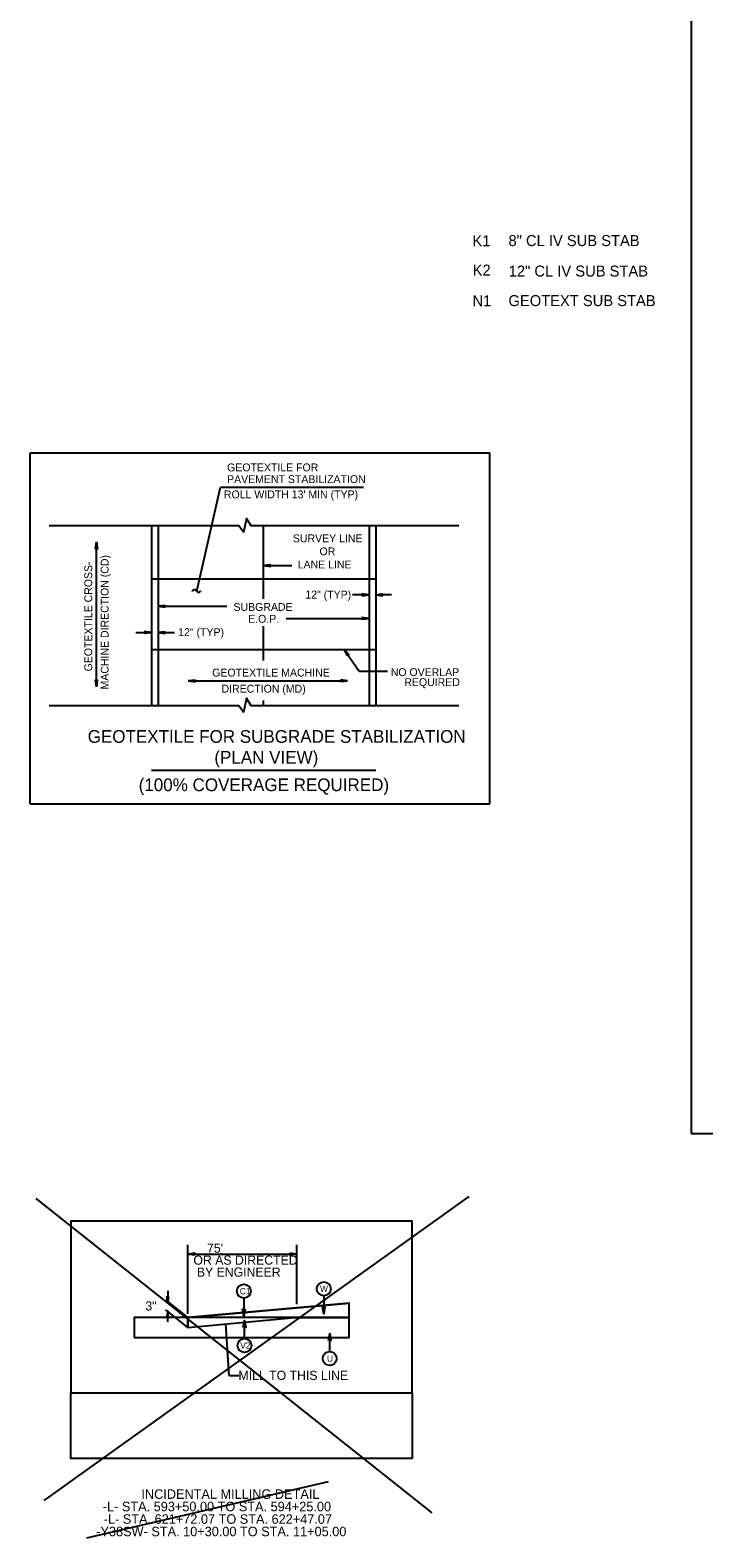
# Model space of a CAD drawing. Extents: x 2294342 to 2294901, y 719427 to 719941.
# Drawn here: x 2294341.9 to 2294456.7, y 719427.3 to 719684.2 of the extents above; entities that cross this region are included whole.
import ezdxf

# ---------------------------------------------------------------- set-up
doc = ezdxf.new("R2010")
doc.units = 0
for name, color, linetype in [('Exist Utilities Sanitary Sewer UG Line', 7, 'Continuous'), ('Old_Level_1', 7, 'Continuous'), ('Old_Level_11', 7, 'Continuous'), ('Old_Level_21', 7, 'Continuous'), ('Prop Dimension Text', 7, 'Continuous'), ('Prop Shade Light', 7, 'Continuous'), ('Raster_Level_2', 7, 'Continuous'), ('Sheet Cutting Line CELL', 7, 'Continuous'), ('Typical Detail Wedge2 CELL', 7, 'Continuous'), ('Typical ID Circle CELL', 7, 'Continuous'), ('Typical Pavement Slope CELL', 7, 'Continuous'), ('Typical Terminator CELL', 7, 'Continuous'), ('Typical Text General CELL', 7, 'Continuous'), ('Typical Text ID Circle CELL', 7, 'Continuous')]:
    doc.layers.add(name, color=color, linetype=linetype)

msp = doc.modelspace()

# ---------------------------------------------------------------- linework, layer by layer
at = {"layer": 'Exist Utilities Sanitary Sewer UG Line'}
msp.add_lwpolyline([(2294359.61, 719461.38), (2294396.24, 719461.38), (2294396.24, 719464.8), (2294359.61, 719464.8)], close=True, dxfattribs=at)
at = {"layer": 'Old_Level_1'}
for p, q in [((2294410.43, 719431.5), (2294342.9, 719485.08)), ((2294344.3, 719433.6), (2294416.73, 719485.43)), ((2294351.54, 719427.26), (2294392.73, 719436.87))]:
    msp.add_line(p, q, dxfattribs=at)
at = {"layer": 'Old_Level_11'}
for q in [(2294375.24, 719463.69), (2294377.46, 719454.94)]:
    msp.add_line((2294375.79, 719454.94), q, dxfattribs=at)
at = {"layer": 'Prop Dimension Text'}
for p, q in [((2294370.28, 719588.6), (2294374.35, 719606.29)), ((2294374.35, 719606.29), (2294398.7, 719606.29)), ((2294362.55, 719599.73), (2294362.55, 719569.07)), ((2294363.7, 719599.73), (2294363.7, 719569.07)), ((2294381.68, 719587.28), (2294381.68, 719599.73)), ((2294399.65, 719599.73), (2294399.65, 719569.07)), ((2294400.8, 719599.73), (2294400.8, 719569.07)), ((2294353.2, 719596.98), (2294353.03, 719595.77)), ((2294353.06, 719595.79), (2294353.2, 719596.98)), ((2294353.2, 719596.98), (2294353.08, 719595.82)), ((2294353.1, 719595.84), (2294353.2, 719596.98)), ((2294353.2, 719596.98), (2294353.13, 719595.86)), ((2294353.15, 719595.88), (2294353.2, 719596.98)), ((2294353.2, 719596.98), (2294353.17, 719595.91)), ((2294353.2, 719596.98), (2294353.36, 719595.77)), ((2294353.2, 719595.93), (2294353.2, 719596.98)), ((2294353.22, 719595.91), (2294353.2, 719596.98)), ((2294353.2, 719596.98), (2294353.24, 719595.88)), ((2294353.27, 719595.86), (2294353.2, 719596.98)), ((2294353.2, 719596.98), (2294353.29, 719595.84)), ((2294353.32, 719595.82), (2294353.2, 719596.98)), ((2294353.2, 719596.98), (2294353.34, 719595.79)), ((2294353.2, 719572.27), (2294353.2, 719596.98)), ((2294353.03, 719595.77), (2294353.2, 719595.93)), ((2294353.2, 719595.93), (2294353.36, 719595.77)), ((2294381.68, 719592.94), (2294382.89, 719593.11)), ((2294381.68, 719592.94), (2294382.86, 719593.08)), ((2294382.84, 719593.06), (2294381.68, 719592.94)), ((2294381.68, 719592.94), (2294382.82, 719593.04)), ((2294382.8, 719593.01), (2294381.68, 719592.94)), ((2294381.68, 719592.94), (2294382.78, 719592.99)), ((2294382.75, 719592.97), (2294381.68, 719592.94)), ((2294381.68, 719592.94), (2294382.89, 719592.78)), ((2294382.86, 719592.8), (2294381.68, 719592.94)), ((2294381.68, 719592.94), (2294382.84, 719592.83)), ((2294382.82, 719592.85), (2294381.68, 719592.94)), ((2294381.68, 719592.94), (2294382.8, 719592.87)), ((2294382.78, 719592.9), (2294381.68, 719592.94)), ((2294381.68, 719592.94), (2294382.75, 719592.92)), ((2294382.73, 719592.94), (2294381.68, 719592.94)), ((2294381.68, 719592.94), (2294386.49, 719592.94)), ((2294382.73, 719592.94), (2294382.89, 719593.11)), ((2294382.89, 719592.78), (2294382.73, 719592.94)), ((2294362.55, 719590.71), (2294400.8, 719590.71)), ((2294370.06, 719588.75), (2294370.49, 719588.45)), ((2294370.9, 719588.55), (2294370.98, 719588.7)), ((2294363.7, 719586.01), (2294364.91, 719586.18)), ((2294363.7, 719586.01), (2294364.89, 719586.15)), ((2294364.86, 719586.13), (2294363.7, 719586.01)), ((2294363.7, 719586.01), (2294364.84, 719586.11)), ((2294364.82, 719586.08), (2294363.7, 719586.01)), ((2294364.75, 719586.01), (2294364.91, 719586.18)), ((2294369.54, 719588.53), (2294369.59, 719588.64)), ((2294399.65, 719587.96), (2294396.84, 719587.96)), ((2294399.65, 719587.96), (2294398.44, 719588.13)), ((2294398.6, 719587.96), (2294398.44, 719588.13)), ((2294399.65, 719587.96), (2294398.44, 719587.8)), ((2294398.44, 719587.8), (2294398.6, 719587.96)), ((2294399.65, 719587.96), (2294398.46, 719588.1)), ((2294398.46, 719587.82), (2294399.65, 719587.96)), ((2294398.49, 719588.08), (2294399.65, 719587.96)), ((2294399.65, 719587.96), (2294398.49, 719587.85)), ((2294399.65, 719587.96), (2294398.51, 719588.06)), ((2294398.51, 719587.87), (2294399.65, 719587.96)), ((2294398.53, 719588.03), (2294399.65, 719587.96)), ((2294399.65, 719587.96), (2294398.53, 719587.89)), ((2294399.65, 719587.96), (2294398.55, 719588.01)), ((2294398.55, 719587.92), (2294399.65, 719587.96)), ((2294398.58, 719587.99), (2294399.65, 719587.96)), ((2294399.65, 719587.96), (2294398.58, 719587.94)), ((2294398.6, 719587.96), (2294399.65, 719587.96)), ((2294400.8, 719587.96), (2294402.01, 719588.13)), ((2294401.99, 719588.1), (2294400.8, 719587.96)), ((2294400.8, 719587.96), (2294401.96, 719588.08)), ((2294401.94, 719588.06), (2294400.8, 719587.96)), ((2294400.8, 719587.96), (2294401.92, 719588.03)), ((2294401.9, 719588.01), (2294400.8, 719587.96)), ((2294400.8, 719587.96), (2294401.87, 719587.99)), ((2294403.46, 719587.96), (2294400.8, 719587.96)), ((2294400.8, 719587.96), (2294402.01, 719587.8)), ((2294401.85, 719587.96), (2294400.8, 719587.96)), ((2294401.87, 719587.94), (2294400.8, 719587.96)), ((2294400.8, 719587.96), (2294401.9, 719587.92)), ((2294401.92, 719587.89), (2294400.8, 719587.96)), ((2294400.8, 719587.96), (2294401.94, 719587.87)), ((2294401.96, 719587.85), (2294400.8, 719587.96)), ((2294400.8, 719587.96), (2294401.99, 719587.82)), ((2294402.01, 719588.13), (2294401.85, 719587.96)), ((2294401.85, 719587.96), (2294402.01, 719587.8)), ((2294363.7, 719586.01), (2294364.8, 719586.06)), ((2294364.77, 719586.04), (2294363.7, 719586.01)), ((2294363.7, 719586.01), (2294364.91, 719585.85)), ((2294364.89, 719585.87), (2294363.7, 719586.01)), ((2294363.7, 719586.01), (2294364.86, 719585.9)), ((2294364.84, 719585.92), (2294363.7, 719586.01)), ((2294363.7, 719586.01), (2294364.82, 719585.95)), ((2294364.8, 719585.97), (2294363.7, 719586.01)), ((2294363.7, 719586.01), (2294364.77, 719585.99)), ((2294364.75, 719586.01), (2294363.7, 719586.01)), ((2294363.7, 719586.01), (2294375.44, 719586.01)), ((2294364.91, 719585.85), (2294364.75, 719586.01)), ((2294385.5, 719583.96), (2294399.65, 719583.96)), ((2294399.65, 719583.96), (2294398.44, 719584.12)), ((2294398.44, 719584.12), (2294398.6, 719583.96)), ((2294399.65, 719583.96), (2294398.44, 719583.79)), ((2294398.6, 719583.96), (2294398.44, 719583.79)), ((2294398.46, 719584.1), (2294399.65, 719583.96)), ((2294399.65, 719583.96), (2294398.46, 719583.82)), ((2294399.65, 719583.96), (2294398.49, 719584.07)), ((2294398.49, 719583.84), (2294399.65, 719583.96)), ((2294398.51, 719584.05), (2294399.65, 719583.96)), ((2294399.65, 719583.96), (2294398.51, 719583.86)), ((2294399.65, 719583.96), (2294398.53, 719584.03)), ((2294398.53, 719583.89), (2294399.65, 719583.96)), ((2294398.55, 719584), (2294399.65, 719583.96)), ((2294399.65, 719583.96), (2294398.55, 719583.91)), ((2294399.65, 719583.96), (2294398.58, 719583.98)), ((2294398.58, 719583.93), (2294399.65, 719583.96)), ((2294398.6, 719583.96), (2294399.65, 719583.96)), ((2294359.89, 719581.56), (2294362.55, 719581.56)), ((2294362.55, 719581.56), (2294361.34, 719581.72)), ((2294361.34, 719581.72), (2294361.5, 719581.56)), ((2294362.55, 719581.56), (2294361.34, 719581.39)), ((2294361.5, 719581.56), (2294361.34, 719581.39)), ((2294361.36, 719581.7), (2294362.55, 719581.56)), ((2294362.55, 719581.56), (2294361.36, 719581.42)), ((2294362.55, 719581.56), (2294361.39, 719581.67)), ((2294361.39, 719581.44), (2294362.55, 719581.56)), ((2294361.41, 719581.65), (2294362.55, 719581.56)), ((2294362.55, 719581.56), (2294361.41, 719581.46)), ((2294362.55, 719581.56), (2294361.43, 719581.63)), ((2294361.43, 719581.49), (2294362.55, 719581.56)), ((2294361.45, 719581.6), (2294362.55, 719581.56)), ((2294362.55, 719581.56), (2294361.45, 719581.51)), ((2294362.55, 719581.56), (2294361.48, 719581.58)), ((2294361.48, 719581.53), (2294362.55, 719581.56)), ((2294361.5, 719581.56), (2294362.55, 719581.56)), ((2294363.7, 719581.56), (2294364.91, 719581.72)), ((2294363.7, 719581.56), (2294364.89, 719581.7)), ((2294364.86, 719581.67), (2294363.7, 719581.56)), ((2294363.7, 719581.56), (2294364.84, 719581.65)), ((2294364.82, 719581.63), (2294363.7, 719581.56)), ((2294363.7, 719581.56), (2294364.8, 719581.6)), ((2294364.77, 719581.58), (2294363.7, 719581.56)), ((2294363.7, 719581.56), (2294366.51, 719581.56)), ((2294363.7, 719581.56), (2294364.91, 719581.39)), ((2294364.89, 719581.42), (2294363.7, 719581.56)), ((2294363.7, 719581.56), (2294364.86, 719581.44)), ((2294364.84, 719581.46), (2294363.7, 719581.56)), ((2294363.7, 719581.56), (2294364.82, 719581.49)), ((2294364.8, 719581.51), (2294363.7, 719581.56)), ((2294363.7, 719581.56), (2294364.77, 719581.53)), ((2294364.75, 719581.56), (2294363.7, 719581.56)), ((2294364.75, 719581.56), (2294364.91, 719581.72)), ((2294364.91, 719581.39), (2294364.75, 719581.56)), ((2294381.68, 719576.77), (2294381.68, 719582.65)), ((2294362.55, 719578.66), (2294400.8, 719578.66)), ((2294395.41, 719578.66), (2294395.98, 719577.58)), ((2294395.41, 719578.66), (2294396.25, 719577.77)), ((2294396.21, 719577.77), (2294395.41, 719578.66)), ((2294395.41, 719578.66), (2294396.18, 719577.78)), ((2294396.15, 719577.78), (2294395.41, 719578.66)), ((2294395.41, 719578.66), (2294396.12, 719577.79)), ((2294396.09, 719577.79), (2294395.41, 719578.66)), ((2294395.41, 719578.66), (2294396.05, 719577.8)), ((2294396.02, 719577.8), (2294395.41, 719578.66)), ((2294396.02, 719577.77), (2294395.41, 719578.66)), ((2294395.41, 719578.66), (2294396.01, 719577.74)), ((2294396, 719577.71), (2294395.41, 719578.66)), ((2294395.41, 719578.66), (2294396, 719577.67)), ((2294395.99, 719577.64), (2294395.41, 719578.66)), ((2294395.41, 719578.66), (2294395.99, 719577.61)), ((2294395.41, 719578.66), (2294397.99, 719574.96)), ((2294396.02, 719577.8), (2294395.98, 719577.58)), ((2294396.25, 719577.77), (2294396.02, 719577.8)), ((2294353.2, 719572.27), (2294353.03, 719573.48)), ((2294353.2, 719573.33), (2294353.03, 719573.48)), ((2294353.2, 719572.27), (2294353.06, 719573.46)), ((2294353.08, 719573.44), (2294353.2, 719572.27)), ((2294353.2, 719572.27), (2294353.1, 719573.42)), ((2294353.13, 719573.39), (2294353.2, 719572.27)), ((2294353.2, 719572.27), (2294353.15, 719573.37)), ((2294353.17, 719573.35), (2294353.2, 719572.27)), ((2294353.2, 719572.27), (2294353.36, 719573.48)), ((2294353.36, 719573.48), (2294353.2, 719573.33)), ((2294353.34, 719573.46), (2294353.2, 719572.27)), ((2294353.2, 719572.27), (2294353.31, 719573.44)), ((2294353.29, 719573.42), (2294353.2, 719572.27)), ((2294353.2, 719572.27), (2294353.27, 719573.39)), ((2294353.24, 719573.37), (2294353.2, 719572.27)), ((2294353.2, 719572.27), (2294353.22, 719573.35)), ((2294353.2, 719573.33), (2294353.2, 719572.27)), ((2294368.85, 719573.31), (2294370.06, 719573.47)), ((2294368.85, 719573.31), (2294370.04, 719573.45)), ((2294370.02, 719573.43), (2294368.85, 719573.31)), ((2294368.85, 719573.31), (2294369.99, 719573.4)), ((2294369.97, 719573.38), (2294368.85, 719573.31)), ((2294368.85, 719573.31), (2294369.95, 719573.35)), ((2294369.93, 719573.33), (2294368.85, 719573.31)), ((2294368.85, 719573.31), (2294370.06, 719573.14)), ((2294370.04, 719573.17), (2294368.85, 719573.31)), ((2294368.85, 719573.31), (2294370.02, 719573.19)), ((2294369.99, 719573.21), (2294368.85, 719573.31)), ((2294368.85, 719573.31), (2294369.97, 719573.24)), ((2294369.95, 719573.26), (2294368.85, 719573.31)), ((2294368.85, 719573.31), (2294369.93, 719573.28)), ((2294369.9, 719573.31), (2294368.85, 719573.31)), ((2294368.85, 719573.31), (2294396, 719573.31)), ((2294369.9, 719573.31), (2294370.06, 719573.47)), ((2294370.06, 719573.14), (2294369.9, 719573.31)), ((2294396, 719573.31), (2294394.78, 719573.47)), ((2294394.78, 719573.47), (2294394.94, 719573.31)), ((2294396, 719573.31), (2294394.78, 719573.15)), ((2294394.94, 719573.31), (2294394.78, 719573.15)), ((2294394.81, 719573.45), (2294396, 719573.31)), ((2294396, 719573.31), (2294394.81, 719573.17)), ((2294396, 719573.31), (2294394.83, 719573.43)), ((2294394.83, 719573.19), (2294396, 719573.31)), ((2294394.85, 719573.4), (2294396, 719573.31)), ((2294396, 719573.31), (2294394.85, 719573.21)), ((2294396, 719573.31), (2294394.88, 719573.38)), ((2294394.88, 719573.24), (2294396, 719573.31)), ((2294394.9, 719573.36), (2294396, 719573.31)), ((2294396, 719573.31), (2294394.9, 719573.26)), ((2294396, 719573.31), (2294394.92, 719573.33)), ((2294394.92, 719573.29), (2294396, 719573.31)), ((2294394.94, 719573.31), (2294396, 719573.31)), ((2294397.99, 719574.96), (2294402.78, 719574.96)), ((2294381.68, 719569.07), (2294381.68, 719569.94)), ((2294362.55, 719558.07), (2294400.8, 719558.07))]:
    msp.add_line(p, q, dxfattribs=at)
for points in [[(2294414.96, 719599.73), (2294379.56, 719599.73), (2294378.77, 719600.98), (2294378.26, 719598.64), (2294377.44, 719599.73), (2294345.12, 719599.73)], [(2294414.96, 719569.07), (2294379.56, 719569.07), (2294378.77, 719570.33), (2294378.26, 719567.99), (2294377.44, 719569.07), (2294345.12, 719569.07)]]:
    msp.add_lwpolyline(points, dxfattribs=at)
for centre, radius, start, end in [((2294369.87, 719588.53), 0.293, 48.0321, 157.831), ((2294370.65, 719588.65), 0.26, 230.477, 338.7625)]:
    msp.add_arc(centre, radius, start, end, dxfattribs=at)
at = {"layer": 'Prop Shade Light'}
msp.add_lwpolyline([(2294368.77, 719464.8), (2294368.77, 719463.09), (2294387.08, 719464.8), (2294396.24, 719464.8), (2294396.24, 719467.28)], close=True, dxfattribs=at)
at = {"layer": 'Raster_Level_2'}
for p, q in [((2294368.77, 719465.43), (2294368.77, 719477.22)), ((2294368.77, 719475.62), (2294387.35, 719475.62)), ((2294387.35, 719467.11), (2294387.35, 719477.22)), ((2294365.34, 719469.38), (2294365.34, 719467.59)), ((2294368.77, 719464.8), (2294365.04, 719467.83)), ((2294368.77, 719463.09), (2294365.04, 719466.12)), ((2294365.34, 719464.09), (2294365.34, 719465.88))]:
    msp.add_line(p, q, dxfattribs=at)
at = {"layer": 'Sheet Cutting Line CELL'}
for p, q in [((2294454.52, 719716.17), (2294454.52, 719496.17)), ((2294454.52, 719496.17), (2294791.32, 719496.17))]:
    msp.add_line(p, q, dxfattribs=at)
at = {"layer": 'Typical Detail Wedge2 CELL'}
for p, q in [((2294341.9, 719552.34), (2294341.9, 719612.19)), ((2294420.24, 719552.34), (2294420.24, 719612.19))]:
    msp.add_line(p, q, dxfattribs=at)
at = {"layer": 'Typical ID Circle CELL'}
for p, q in [((2294378.31, 719468.13), (2294378.31, 719465.06)), ((2294391.93, 719468.53), (2294391.93, 719465.46)), ((2294378.42, 719461.22), (2294378.42, 719464.29)), ((2294392.94, 719459.01), (2294392.94, 719462.07))]:
    msp.add_line(p, q, dxfattribs=at)
for centre in [(2294378.31, 719469.31), (2294391.93, 719469.71), (2294378.42, 719460.04), (2294392.94, 719457.82)]:
    msp.add_circle(centre, 1.19, dxfattribs=at)
at = {"layer": 'Typical Pavement Slope CELL'}
for p, q in [((2294368.77, 719464.8), (2294396.24, 719467.28)), ((2294396.24, 719464.8), (2294396.24, 719467.28)), ((2294368.77, 719463.09), (2294387.08, 719464.8)), ((2294368.77, 719463.09), (2294368.77, 719464.8)), ((2294387.08, 719464.8), (2294396.24, 719464.8))]:
    msp.add_line(p, q, dxfattribs=at)
for points in [[(2294348.82, 719451.99), (2294407.02, 719451.99), (2294407.02, 719481.24), (2294348.82, 719481.24)], [(2294407.02, 719440.79), (2294348.81, 719440.79), (2294348.81, 719451.99), (2294407.02, 719451.99)]]:
    msp.add_lwpolyline(points, close=True, dxfattribs=at)
at = {"layer": 'Typical Terminator CELL'}
for points in [[(2294369.92, 719475.43), (2294368.77, 719475.62), (2294369.92, 719475.83), (2294369.77, 719475.62)], [(2294386.2, 719475.82), (2294387.35, 719475.62), (2294386.19, 719475.42), (2294386.34, 719475.62)], [(2294365.47, 719468.36), (2294365.34, 719467.59), (2294365.2, 719468.36), (2294365.34, 719468.26)], [(2294365.47, 719465.11), (2294365.34, 719465.88), (2294365.2, 719465.11), (2294365.34, 719465.21)], [(2294378.51, 719466.21), (2294378.31, 719465.06), (2294378.11, 719466.22), (2294378.31, 719466.07)], [(2294392.13, 719466.61), (2294391.93, 719465.46), (2294391.73, 719466.62), (2294391.93, 719466.47)], [(2294392.13, 719466.61), (2294391.93, 719465.46), (2294391.73, 719466.62), (2294391.93, 719466.47)], [(2294378.22, 719463.14), (2294378.42, 719464.29), (2294378.63, 719463.13), (2294378.42, 719463.28)], [(2294392.74, 719460.92), (2294392.94, 719462.07), (2294393.14, 719460.92), (2294392.94, 719461.07)], [(2294392.74, 719460.92), (2294392.94, 719462.07), (2294393.14, 719460.92), (2294392.94, 719461.07)]]:
    msp.add_lwpolyline(points, close=True, dxfattribs=at)
at = {"layer": 'Typical Text General CELL'}
for p, q in [((2294341.9, 719612.19), (2294420.24, 719612.19)), ((2294341.9, 719552.34), (2294420.24, 719552.34))]:
    msp.add_line(p, q, dxfattribs=at)

# ---------------------------------------------------------------- texts
at = {"layer": 'Old_Level_1'}
for s, height, p in [("    75'", 1.562, (2294369.72, 719475.86)), ('OR AS DIRECTED', 1.5625, (2294369.72, 719473.81)), (' BY ENGINEER', 1.5625, (2294369.72, 719471.77)), ('MILL TO THIS LINE', 1.5625, (2294377.4, 719454.18))]:
    msp.add_text(s, height=height, rotation=360, dxfattribs=at).set_placement(p)
at = {"layer": 'Old_Level_21'}
for s, p in [('K1', (2294417.27, 719647.36)), ('8" CL IV SUB STAB', (2294423.41, 719647.4)), ('K2', (2294417.31, 719642.37)), ('12" CL IV SUB STAB', (2294423.45, 719642.21)), ('N1', (2294417.27, 719637.14)), ('GEOTEXT SUB STAB', (2294423.41, 719637.17))]:
    msp.add_text(s, height=1.875, dxfattribs=at).set_placement(p)
at = {"layer": 'Prop Dimension Text'}
for s, height, p in [('GEOTEXTILE FOR', 1.3411, (2294375.46, 719609.01)), ('PAVEMENT STABILIZATION', 1.3411, (2294375.46, 719607.01)), ("ROLL WIDTH 13' MIN (TYP)", 1.3411, (2294374.92, 719604.41)), ('SURVEY LINE', 1.3411, (2294386.67, 719596.92)), ('LANE LINE', 1.341, (2294387.5, 719592.47)), ('OR', 1.341, (2294391.21, 719594.7)), ('12" (TYP)', 1.341, (2294388.79, 719587.34)), ('SUBGRADE', 1.341, (2294376.55, 719585.23)), ('E.O.P.', 1.341, (2294379.05, 719583.21)), ('12" (TYP)', 1.341, (2294367.12, 719580.94)), ('NO OVERLAP ', 1.3411, (2294403.35, 719574.12)), ('REQUIRED', 1.341, (2294405.66, 719572.42)), ('3"', 1.562, (2294361.53, 719466.01))]:
    msp.add_text(s, height=height, dxfattribs=at).set_placement(p)
for s, height, rotation, p in [('MACHINE DIRECTION (CD)', 1.3411, 90, (2294355.26, 719571.84)), ('GEOTEXTILE CROSS-', 1.3411, 90, (2294352.47, 719574.92)), ('GEOTEXTILE MACHINE', 1.3411, 360, (2294372.92, 719574.05)), ('DIRECTION (MD)', 1.3411, 360, (2294374.51, 719571.3)), ('GEOTEXTILE FOR SUBGRADE STABILIZATION ', 2.167, 360, (2294351.7, 719562.75)), ('(PLAN VIEW)', 2.167, 360, (2294373.29, 719559.2)), ('(100% COVERAGE REQUIRED)', 2.167, 360, (2294360.39, 719554.51))]:
    msp.add_text(s, height=height, rotation=rotation, dxfattribs=at).set_placement(p)
at = {"layer": 'Typical Pavement Slope CELL'}
for s, p in [('INCIDENTAL MILLING DETAIL', (2294360.86, 719433.91)), ('-L- STA. 593+50.00 TO STA. 594+25.00', (2294354.28, 719431.79)), ('-L- STA. 621+72.07 TO STA. 622+47.07', (2294354.44, 719429.66)), ('-Y38SW- STA. 10+30.00 TO STA. 11+05.00', (2294353.16, 719427.54))]:
    msp.add_text(s, height=1.6199, rotation=360, dxfattribs=at).set_placement(p)
at = {"layer": 'Typical Text ID Circle CELL'}
for s, height, p in [('C1', 1.062, (2294377.62, 719468.78)), ('W', 1.06, (2294391.3, 719469.18)), ('V2', 1.062, (2294377.69, 719459.51)), ('U', 1.06, (2294392.48, 719457.29))]:
    msp.add_text(s, height=height, rotation=360, dxfattribs=at).set_placement(p)

doc.saveas('drawing.dxf')
